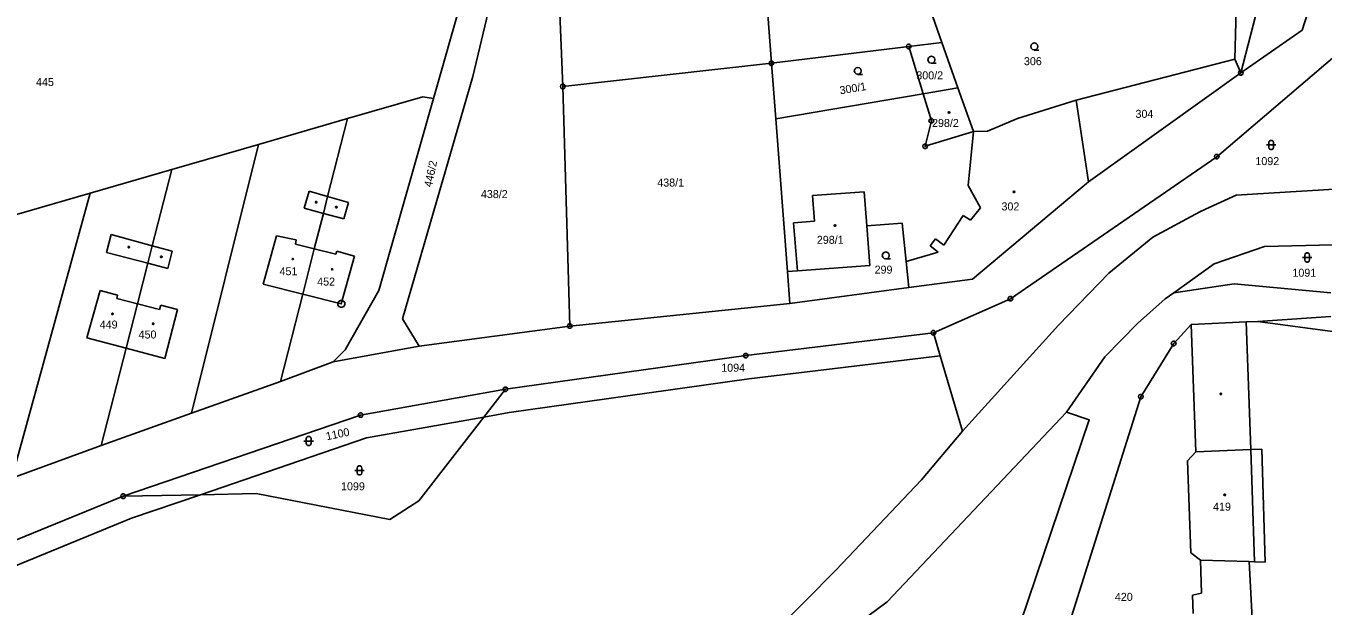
# Model space of a CAD drawing. Extents: x -812394 to -807601, y -1013098 to -1009266.
# Drawn here: x -811273.1 to -810997.6, y -1011712.3 to -1011589.1 of the extents above; entities that cross this region are included whole.
import ezdxf

# ---------------------------------------------------------------- set-up
doc = ezdxf.new("R2010")
doc.units = 0
for name, color, linetype in [('KN_HRANICE', 7, 'Continuous'), ('KN_KULTURY', 7, 'Continuous'), ('KN_MEZNIKY', 7, 'Continuous'), ('KN_PARCELY', 7, 'Continuous'), ('KN_SLUCKY', 7, 'Continuous')]:
    doc.layers.add(name, color=color, linetype=linetype)

# ---------------------------------------------------------------- blocks, each defined once
blk = doc.blocks.new('101')
blk.add_line((-0.05, 0), (0.05, 0))
blk.add_lwpolyline([(0.19, 0.72), (0.53, 0.53), (0.72, 0.19), (0.72, -0.2), (0.53, -0.54), (0.19, -0.73), (-0.2, -0.73), (-0.54, -0.54), (-0.73, -0.2), (-0.73, 0.19), (-0.54, 0.53), (-0.2, 0.72), (0.19, 0.72)])
blk = doc.blocks.new('304')
blk.add_lwpolyline([(0, 0), (-0.38, 0.1), (-0.65, 0.37), (-0.75, 0.74), (-0.65, 1.11), (-0.38, 1.38), (-0.01, 1.48), (0.36, 1.38), (0.63, 1.11), (0.73, 0.73), (0.63, 0.35), (0.36, 0.08), (-0.02, -0.02), (0.98, -0.02)])
blk = doc.blocks.new('316')
for points in [[(-1, 1), (0.27, 1), (1, 1)], [(-0.5, 1.5), (-0.4, 1.79), (-0.15, 1.97), (0.16, 1.97), (0.41, 1.79), (0.51, 1.5), (0.51, 0.5), (0.41, 0.21), (0.16, 0.03), (-0.15, 0.03), (-0.4, 0.21), (-0.5, 0.5), (-0.5, 1.5)]]:
    blk.add_lwpolyline(points)
blk = doc.blocks.new('NAHRADNI_SYMBOL')
blk.add_lwpolyline([(0.09, 0.15), (0.18, 0), (0.09, -0.15), (-0.09, -0.15), (-0.18, 0), (-0.09, 0.15), (0.09, 0.15)])
blk = doc.blocks.new('402')
blk.add_lwpolyline([(0.09, 0.15), (0.18, 0), (0.09, -0.15), (-0.09, -0.15), (-0.18, 0), (-0.09, 0.15), (0.09, 0.15)])
blk = doc.blocks.new('105')
blk.add_line((-0.12, 0), (0.12, 0))
blk.add_lwpolyline([(0.15, 0.48), (0.4, 0.3), (0.5, 0.01), (0.4, -0.28), (0.15, -0.46), (-0.16, -0.46), (-0.41, -0.28), (-0.51, 0.01), (-0.41, 0.3), (-0.16, 0.48), (0.15, 0.48)])

msp = doc.modelspace()

# ---------------------------------------------------------------- linework, layer by layer
at = {"layer": 'KN_HRANICE'}
for p, q in [((-811178.18, -1011599.83), (-811166.46, -1011550.55)), ((-811078.55, -1011592.58), (-811086.24, -1011570.61)), ((-811008.1, -1011572.3), (-811015.03, -1011599.04)), ((-811114.74, -1011597.01), (-811116.42, -1011574.14)), ((-811186.53, -1011604.51), (-811179.22, -1011578.9)), ((-811159.98, -1011578.81), (-811159.05, -1011601.95)), ((-811001.99, -1011589.96), (-810998.41, -1011578.57)), ((-811016.02, -1011585.65), (-811016.27, -1011596.11)), ((-811015.03, -1011599.04), (-811001.99, -1011589.96)), ((-811114.74, -1011597.01), (-811085.57, -1011593.44)), ((-811085.57, -1011593.44), (-811078.55, -1011592.58)), ((-811082.51, -1011603.49), (-811085.57, -1011593.44)), ((-811078.55, -1011592.58), (-811075.12, -1011602.24)), ((-811159.05, -1011601.95), (-811114.74, -1011597.01)), ((-811113.84, -1011608.78), (-811114.74, -1011597.01)), ((-811049.99, -1011604.85), (-811016.27, -1011596.11)), ((-811020.14, -1011616.85), (-810994.59, -1011595.07)), ((-811015.03, -1011599.04), (-811016.27, -1011596.11)), ((-811193.09, -1011651.29), (-811178.18, -1011599.83)), ((-811047.37, -1011622.22), (-811015.03, -1011599.04)), ((-811159.05, -1011601.95), (-811157.58, -1011652.84)), ((-811075.12, -1011602.24), (-811082.51, -1011603.49)), ((-811075.12, -1011602.24), (-811071.83, -1011611.51)), ((-811204.79, -1011608.77), (-811188.82, -1011604.14)), ((-811198.15, -1011645.26), (-811186.53, -1011604.51)), ((-811188.82, -1011604.14), (-811186.53, -1011604.51)), ((-811082.51, -1011603.49), (-811113.84, -1011608.78)), ((-811080.76, -1011609.22), (-811082.51, -1011603.49)), ((-811062.46, -1011608.77), (-811049.99, -1011604.85)), ((-811047.37, -1011622.22), (-811049.99, -1011604.85)), ((-811223.68, -1011614.25), (-811204.79, -1011608.77)), ((-811209.02, -1011625.33), (-811204.79, -1011608.77)), ((-811111.34, -1011641.25), (-811113.84, -1011608.78)), ((-811082.09, -1011614.65), (-811080.76, -1011609.22)), ((-811068.83, -1011611.45), (-811062.46, -1011608.77)), ((-811071.83, -1011611.51), (-811082.09, -1011614.65)), ((-811072.96, -1011622.96), (-811071.83, -1011611.51)), ((-811071.83, -1011611.51), (-811068.83, -1011611.45)), ((-811242.11, -1011619.59), (-811223.68, -1011614.25)), ((-811237.94, -1011671.39), (-811223.68, -1011614.25)), ((-811063.97, -1011647.03), (-811020.14, -1011616.85)), ((-811259.45, -1011624.61), (-811242.11, -1011619.59)), ((-811246.26, -1011635.77), (-811242.11, -1011619.59)), ((-811276.13, -1011685.2), (-811259.45, -1011624.61)), ((-811275.14, -1011629.16), (-811259.45, -1011624.61)), ((-811070.33, -1011627.71), (-811072.96, -1011622.96)), ((-811072.01, -1011642.87), (-811047.37, -1011622.22)), ((-811209.93, -1011628.91), (-811209.02, -1011625.33)), ((-811211.85, -1011636.43), (-811209.93, -1011628.91)), ((-811074.03, -1011629.35), (-811078.1, -1011635.68)), ((-811072.48, -1011630.33), (-811074.03, -1011629.35)), ((-811070.33, -1011627.71), (-811072.48, -1011630.33)), ((-811033.74, -1011633.95), (-811023.75, -1011628.6)), ((-811023.75, -1011628.6), (-811022.52, -1011628.03)), ((-811094.5, -1011631.56), (-811086.99, -1011630.95)), ((-811094.5, -1011631.56), (-811093.86, -1011639.95)), ((-811086.99, -1011630.95), (-811086.11, -1011639.13)), ((-811247.2, -1011639.45), (-811246.26, -1011635.77)), ((-811079.86, -1011634.34), (-811081.05, -1011635.82)), ((-811081.05, -1011635.82), (-811079.35, -1011637.16)), ((-811078.1, -1011635.68), (-811079.86, -1011634.34)), ((-811043.08, -1011641.62), (-811033.74, -1011633.95)), ((-811214.31, -1011646.05), (-811211.85, -1011636.43)), ((-811086.11, -1011639.13), (-811079.35, -1011637.16)), ((-811249.43, -1011648.14), (-811247.2, -1011639.45)), ((-811109.22, -1011641.09), (-811111.34, -1011641.25)), ((-811110.82, -1011648.06), (-811111.34, -1011641.25)), ((-811093.86, -1011639.95), (-811109.22, -1011641.09)), ((-811086.11, -1011639.13), (-811085.52, -1011644.68)), ((-811085.52, -1011644.68), (-811072.01, -1011642.87)), ((-811053.75, -1011652.65), (-811043.08, -1011641.62)), ((-811016.44, -1011643.9), (-811029.29, -1011645.78)), ((-810995.89, -1011645.77), (-811016.44, -1011643.9)), ((-811219.05, -1011664.64), (-811214.31, -1011646.05)), ((-811205.32, -1011657.9), (-811198.15, -1011645.26)), ((-811110.82, -1011648.06), (-811085.52, -1011644.68)), ((-811251.85, -1011657.56), (-811249.43, -1011648.14)), ((-811110.82, -1011648.06), (-811157.58, -1011652.84)), ((-811080.33, -1011654.28), (-811063.97, -1011647.03)), ((-811189.59, -1011657.14), (-811193.09, -1011651.29)), ((-811013.86, -1011651.97), (-811025.55, -1011652.51)), ((-811011.38, -1011651.85), (-811013.86, -1011651.97)), ((-811011.38, -1011651.85), (-810995.89, -1011650.79)), ((-810971.7, -1011657.24), (-811011.38, -1011651.85)), ((-811189.59, -1011657.14), (-811157.58, -1011652.84)), ((-811120.19, -1011659.13), (-811080.33, -1011654.28)), ((-811080.33, -1011654.28), (-811078.89, -1011659.14)), ((-811074.13, -1011675.17), (-811053.75, -1011652.65)), ((-811025.55, -1011652.51), (-811029.28, -1011656.56)), ((-811024.55, -1011679.56), (-811025.55, -1011652.51)), ((-811257.15, -1011678.25), (-811251.85, -1011657.56)), ((-811207.83, -1011660.48), (-811189.59, -1011657.14)), ((-811029.28, -1011656.56), (-811036.27, -1011667.85)), ((-811219.05, -1011664.64), (-811207.83, -1011660.48)), ((-811207.83, -1011660.48), (-811205.32, -1011657.9)), ((-811171.25, -1011666.28), (-811120.19, -1011659.13)), ((-811078.89, -1011659.14), (-811119.54, -1011664.09)), ((-811074.13, -1011675.17), (-811078.89, -1011659.14)), ((-811237.94, -1011671.39), (-811219.05, -1011664.64)), ((-811119.54, -1011664.09), (-811170.46, -1011671.22)), ((-811202.01, -1011671.78), (-811171.25, -1011666.28)), ((-811171.25, -1011666.28), (-811175.83, -1011672.18)), ((-811036.27, -1011667.85), (-811058.25, -1011737.49)), ((-811257.15, -1011678.25), (-811237.94, -1011671.39)), ((-811170.46, -1011671.22), (-811175.83, -1011672.18)), ((-811252.46, -1011689.01), (-811202.01, -1011671.78)), ((-811175.83, -1011672.18), (-811200.75, -1011676.63)), ((-811189.64, -1011689.98), (-811175.83, -1011672.18)), ((-811200.75, -1011676.63), (-811236.06, -1011688.69)), ((-811082.88, -1011685.55), (-811074.13, -1011675.17)), ((-811276.13, -1011685.2), (-811257.15, -1011678.25)), ((-811026.38, -1011681.48), (-811024.55, -1011679.56)), ((-811024.55, -1011679.56), (-811012.93, -1011679.1)), ((-811012.93, -1011679.1), (-811010.59, -1011679.01)), ((-811009.86, -1011703), (-811010.59, -1011679.01)), ((-811025.62, -1011701.03), (-811026.38, -1011681.48)), ((-811101.04, -1011704.72), (-811082.88, -1011685.55)), ((-811305.52, -1011710.63), (-811252.46, -1011689.01)), ((-811236.06, -1011688.69), (-811252.46, -1011689.01)), ((-811236.06, -1011688.69), (-811250.71, -1011693.69)), ((-811236.06, -1011688.69), (-811224.18, -1011688.46)), ((-811224.18, -1011688.46), (-811195.82, -1011693.94)), ((-811195.82, -1011693.94), (-811189.64, -1011689.98)), ((-811250.71, -1011693.69), (-811375.13, -1011744.58)), ((-811025.62, -1011701.03), (-811023.6, -1011702.59)), ((-811113.97, -1011717.72), (-811101.04, -1011704.72)), ((-811023.6, -1011702.59), (-811023.35, -1011709.59)), ((-811023.6, -1011702.59), (-811013.26, -1011702.91)), ((-811013.26, -1011702.91), (-811012.11, -1011702.94)), ((-811012.11, -1011702.94), (-811009.86, -1011703)), ((-811023.35, -1011709.59), (-811025.3, -1011710.01)), ((-811025.3, -1011710.01), (-811025.13, -1011713.95))]:
    msp.add_line(p, q, dxfattribs=at)
for points in [[(-811005.6, -1011624.4), (-811016.01, -1011625.04), (-811022.52, -1011628.03)], [(-810982.75, -1011623.07), (-810983.49, -1011623.04), (-811005.6, -1011624.4)], [(-811029.29, -1011645.78), (-811020.71, -1011639.62), (-811010, -1011635.94), (-810983.72, -1011635.29), (-810982.94, -1011635.34)], [(-811052.04, -1011671.11), (-811043.88, -1011659.38), (-811036.94, -1011652.27), (-811031.09, -1011647.08), (-811029.29, -1011645.78)], [(-811123.04, -1011735.83), (-811090.17, -1011711.42), (-811052.04, -1011671.11)], [(-811074.63, -1011753.78), (-811047.22, -1011672.77), (-811052.04, -1011671.11)]]:
    msp.add_lwpolyline(points, dxfattribs=at)
at = {"layer": 'KN_SLUCKY'}
for p, q in [((-811212.97, -1011624.2), (-811214.03, -1011627.79)), ((-811209.02, -1011625.33), (-811212.97, -1011624.2)), ((-811106.05, -1011625.09), (-811095.06, -1011624.33)), ((-811095.06, -1011624.33), (-811094.5, -1011631.56)), ((-811204.58, -1011626.6), (-811209.02, -1011625.33)), ((-811205.58, -1011630.09), (-811204.58, -1011626.6)), ((-811105.59, -1011630.56), (-811106.05, -1011625.09)), ((-811214.03, -1011627.79), (-811209.93, -1011628.91)), ((-811209.93, -1011628.91), (-811205.58, -1011630.09)), ((-811110.07, -1011630.94), (-811105.59, -1011630.56)), ((-811109.22, -1011641.09), (-811110.07, -1011630.94)), ((-811255.01, -1011633.38), (-811256.02, -1011637.19)), ((-811246.26, -1011635.77), (-811255.01, -1011633.38)), ((-811242.03, -1011636.92), (-811246.26, -1011635.77)), ((-811219.86, -1011633.69), (-811222.71, -1011643.91)), ((-811215.73, -1011634.51), (-811219.86, -1011633.69)), ((-811215.87, -1011635.44), (-811215.73, -1011634.51)), ((-811211.85, -1011636.43), (-811215.87, -1011635.44)), ((-811247.2, -1011639.45), (-811256.02, -1011637.19)), ((-811242.99, -1011640.61), (-811242.03, -1011636.92)), ((-811207.26, -1011637.55), (-811211.85, -1011636.43)), ((-811207.08, -1011636.91), (-811207.26, -1011637.55)), ((-811203.29, -1011637.97), (-811207.08, -1011636.91)), ((-811206.13, -1011648.13), (-811203.29, -1011637.97)), ((-811247.2, -1011639.45), (-811242.99, -1011640.61)), ((-811222.71, -1011643.91), (-811214.31, -1011646.05)), ((-811257.36, -1011645.28), (-811260.18, -1011655.38)), ((-811253.64, -1011646.25), (-811257.36, -1011645.28)), ((-811253.83, -1011646.99), (-811253.64, -1011646.25)), ((-811214.31, -1011646.05), (-811206.13, -1011648.13)), ((-811249.43, -1011648.14), (-811253.83, -1011646.99)), ((-811244.72, -1011649.36), (-811249.43, -1011648.14)), ((-811244.48, -1011648.43), (-811244.72, -1011649.36)), ((-811240.89, -1011649.36), (-811244.48, -1011648.43)), ((-811243.58, -1011659.72), (-811240.89, -1011649.36)), ((-811012.93, -1011679.1), (-811013.86, -1011651.97)), ((-811260.18, -1011655.38), (-811251.85, -1011657.56)), ((-811251.85, -1011657.56), (-811243.58, -1011659.72)), ((-811012.11, -1011702.94), (-811012.93, -1011679.1)), ((-811013.26, -1011702.91), (-811012.49, -1011717.69))]:
    msp.add_line(p, q, dxfattribs=at)

# ---------------------------------------------------------------- block references
at = {"layer": 'KN_KULTURY'}
for name, p in [('304', (-811058.88, -1011594.17)), ('304', (-811080.75, -1011596.98)), ('304', (-811096.38, -1011599.35)), ('NAHRADNI_SYMBOL', (-811077.02, -1011607.45)), ('316', (-811008.57, -1011615.36)), ('NAHRADNI_SYMBOL', (-811063.22, -1011624.33)), ('402', (-811211.46, -1011626.52)), ('402', (-811207.18, -1011627.57)), ('402', (-811101.25, -1011631.5)), ('402', (-811251.25, -1011636.07)), ('402', (-811244.35, -1011638.14)), ('304', (-811090.44, -1011638.56)), ('316', (-811000.94, -1011639.27)), ('402', (-811254.72, -1011650.26)), ('402', (-811246.08, -1011652.35)), ('402', (-811019.27, -1011667.27)), ('316', (-811213.05, -1011678.27)), ('316', (-811202.27, -1011684.52)), ('402', (-811018.44, -1011688.73))]:
    msp.add_blockref(name, p, dxfattribs=at)
at = {"layer": 'KN_KULTURY', "xscale": 0.67, "yscale": 0.67}
for p in [(-811216.41, -1011638.59), (-811208.07, -1011640.78)]:
    msp.add_blockref('402', p, dxfattribs=at)
at = {"layer": 'KN_MEZNIKY'}
for name, p in [('105', (-811085.57, -1011593.44)), ('105', (-811114.74, -1011597.01)), ('105', (-811015.03, -1011599.04)), ('105', (-811159.05, -1011601.95)), ('105', (-811080.76, -1011609.22)), ('105', (-811082.09, -1011614.65)), ('105', (-811020.14, -1011616.85)), ('105', (-811063.97, -1011647.03)), ('101', (-811206.1, -1011648.13)), ('105', (-811157.58, -1011652.84)), ('105', (-811080.33, -1011654.28)), ('105', (-811029.28, -1011656.56)), ('105', (-811120.19, -1011659.13)), ('105', (-811171.25, -1011666.28)), ('105', (-811036.27, -1011667.85)), ('105', (-811202.01, -1011671.78)), ('105', (-811252.46, -1011689.01))]:
    msp.add_blockref(name, p, dxfattribs=at)

# ---------------------------------------------------------------- texts
at = {"layer": 'KN_PARCELY'}
for s, p in [('306', (-811061.1, -1011597.41)), ('300/2', (-811083.96, -1011600.42)), ('445', (-811270.97, -1011601.83)), ('304', (-811037.4, -1011608.6)), ('298/2', (-811080.62, -1011610.54)), ('1092', (-811011.93, -1011618.64)), ('438/1', (-811138.99, -1011623.2)), ('438/2', (-811176.46, -1011625.65)), ('302', (-811065.87, -1011628.27)), ('298/1', (-811105.09, -1011635.37)), ('451', (-811219.24, -1011642.05)), ('299', (-811092.82, -1011641.7)), ('1091', (-811004.06, -1011642.36)), ('452', (-811211.24, -1011644.24)), ('449', (-811257.44, -1011653.37)), ('450', (-811249.18, -1011655.49)), ('1094', (-811125.4, -1011662.55)), ('1099', (-811206.17, -1011687.75)), ('419', (-811020.92, -1011692.07)), ('420', (-811041.78, -1011711.24))]:
    msp.add_text(s, height=1.7, dxfattribs=at).set_placement(p)
for s, rotation, p in [('300/1', 9.626, (-811100.1, -1011603.63)), ('446/2', 78.266, (-811186.9, -1011623.43)), ('1100', 11.574, (-811209.2, -1011677.12))]:
    msp.add_text(s, height=1.7, rotation=rotation, dxfattribs=at).set_placement(p)

doc.saveas('drawing.dxf')
